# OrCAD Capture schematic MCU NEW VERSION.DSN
size A
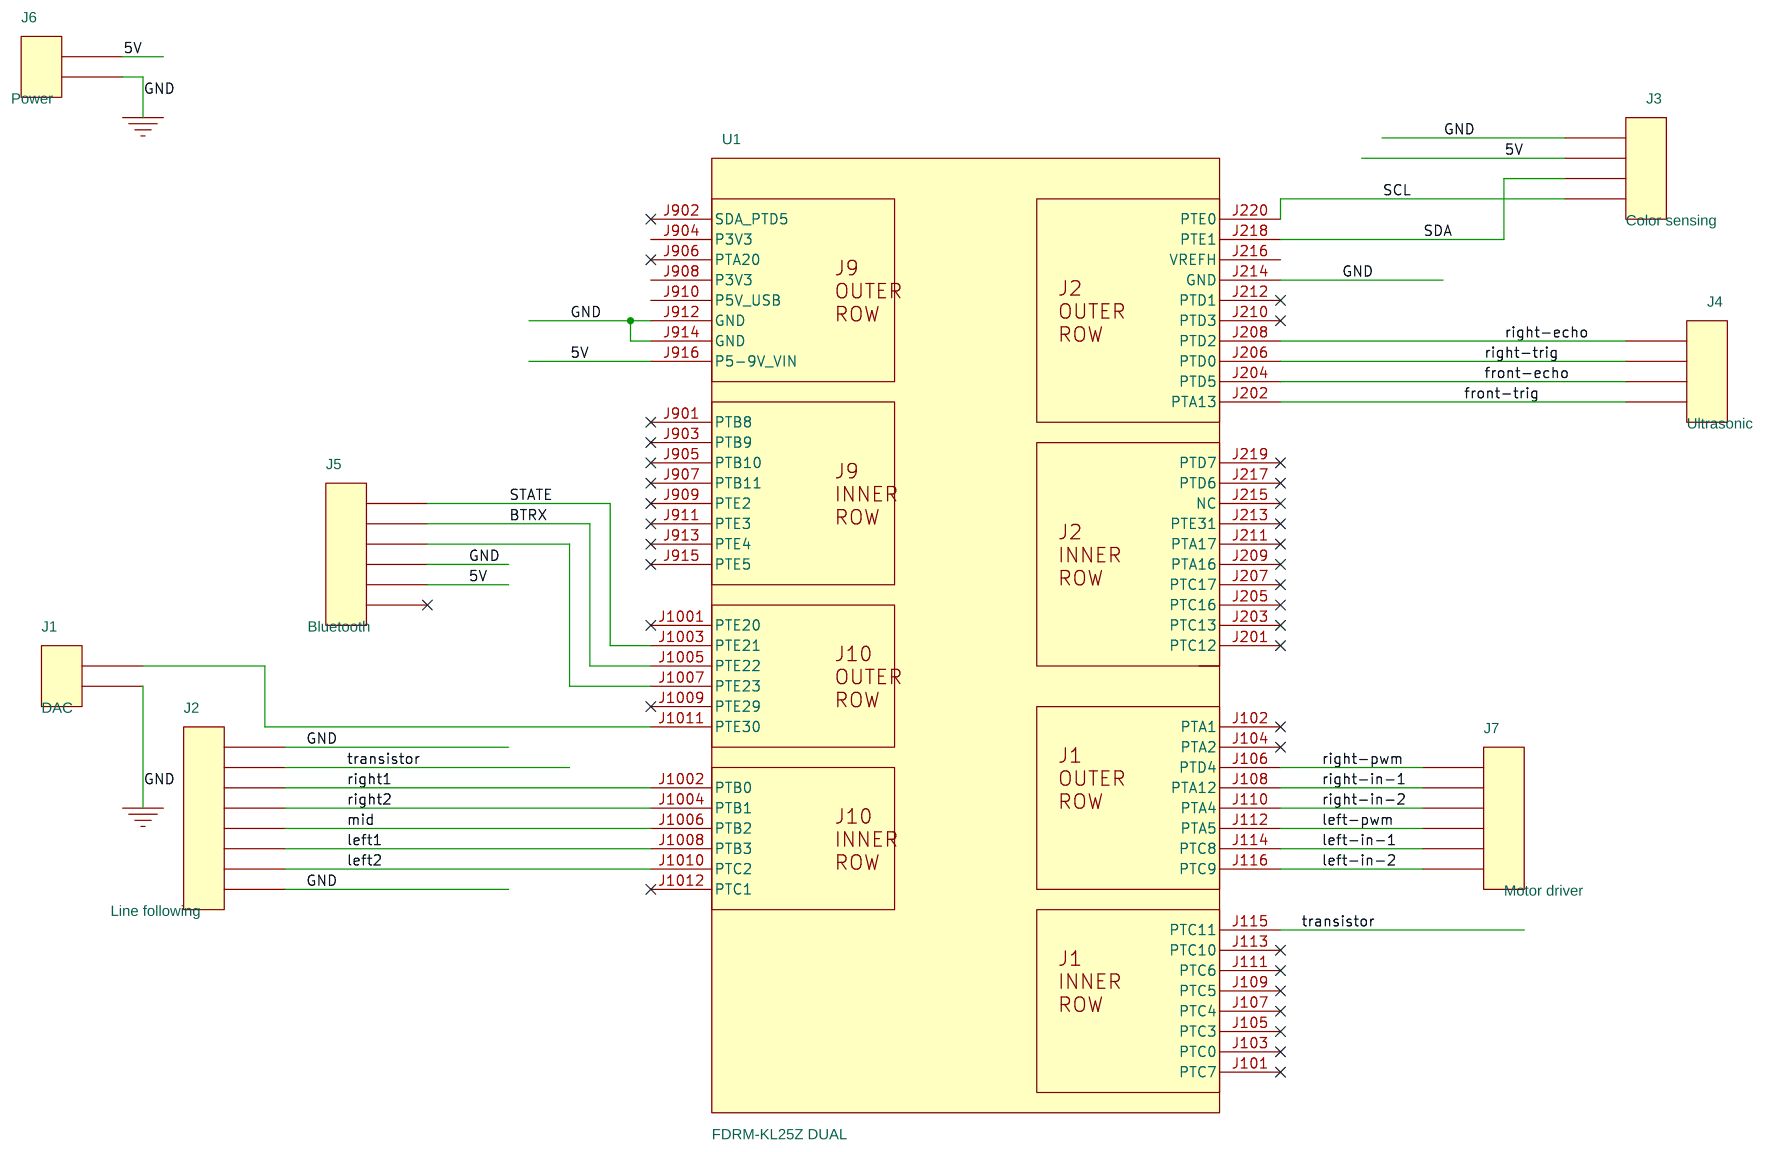
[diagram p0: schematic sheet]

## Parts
J1  DAC  [gu-molex2]
J2  Line following  [gu-molex8]
J3  Color sensing  [gu-molex4]
J4  Ultrasonic  [gu-molex4]
J5  Bluetooth  [gu-molex6]
J6  Power  [gu-molex2]
J7  Motor driver  [gu-molex6]
U1  FDRM-KL25Z DUAL  [gu-frdm-kl25z]

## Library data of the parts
J1 J6 = CON2
J2 = CON8
J3 J4 = CON4
J5 J7 = CON6
U1 = FDRM-KL25Z_DUAL

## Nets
5V: J3.2 J5.5 J6.1 U1.J916(P5-9V_VIN)
GND: J1.2 J2.1 J2.8 J3.1 J5.4 J6.2 U1.J214(GND) U1.J912(GND) U1.J914(GND)
P3V3: U1.J904(P3V3) U1.J908(P3V3)
P5V_USB: U1.J910(P5V_USB)
BTRX: J5.2 U1.J1005(PTE22)
front-echo: J4.3 U1.J204(PTD5)
front-trig: J4.4 U1.J202(PTA13)
left1: J2.6 U1.J1008(PTB3)
left2: J2.7 U1.J1010(PTC2)
left-in-1: J7.5 U1.J114(PTC8)
left-in-2: J7.6 U1.J116(PTC9)
left-pwm: J7.4 U1.J112(PTA5)
mid: J2.5 U1.J1006(PTB2)
right1: J2.3 U1.J1002(PTB0)
right2: J2.4 U1.J1004(PTB1)
right-echo: J4.1 U1.J208(PTD2)
right-in-1: J7.2 U1.J108(PTA12)
right-in-2: J7.3 U1.J110(PTA4)
right-pwm: J7.1 U1.J106(PTD4)
right-trig: J4.2 U1.J206(PTD0)
SCL: J3.4 U1.J220(PTE0)
SDA: J3.3 U1.J218(PTE1)
STATE: J5.1 U1.J1003(PTE21)
transistor: J2.2 U1.J115(PTC11)
VREFH: U1.J216(VREFH)
N00587: J1.1 U1.J1011(PTE30)
N00956: J5.3 U1.J1007(PTE23)

Not connected (* = marked no-connect by the designer): J5 6*; U1 J101(PTC7)* J102(PTA1)* J103(PTC0)* J104(PTA2)* J105(PTC3)* J107(PTC4)* J109(PTC5)* J111(PTC6)* J113(PTC10)* J201(PTC12)* J203(PTC13)* J205(PTC16)* J207(PTC17)* J209(PTA16)* J210(PTD3)* J211(PTA17)* J212(PTD1)* J213(PTE31)* J215(NC)* J217(PTD6)* J219(PTD7)* J901(PTB8)* J902(SDA_PTD5)* J903(PTB9)* J905(PTB10)* J906(PTA20)* J907(PTB11)* J909(PTE2)* J911(PTE3)* J913(PTE4)* J915(PTE5)* J1001(PTE20)* J1009(PTE29)* J1012(PTC1)*
